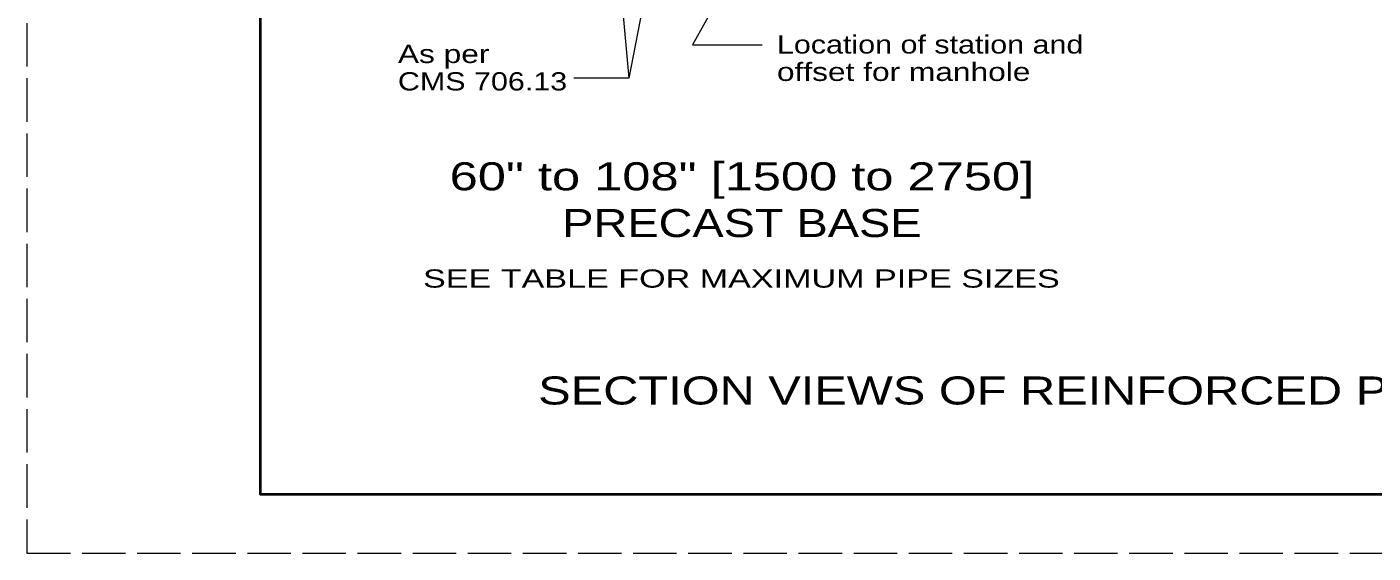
# Model space of a CAD drawing. Extents: x 808.4 to 842.4, y 1034.6 to 1056.6.
# Drawn here: x 808.44 to 819.97, y 1034.63 to 1039.13 of the extents above; entities that cross this region are included whole.
import ezdxf
from ezdxf.enums import TextEntityAlignment as Align

# ---------------------------------------------------------------- set-up
doc = ezdxf.new("R2010")
doc.units = 0
doc.header["$LTSCALE"] = 0.062
doc.linetypes.add('LONG_DASHED', pattern=[7.5, 6, -1.5])
doc.layers.add('1', color=7, linetype='Continuous', lineweight=13)
doc.layers.add('10', color=7, linetype='Continuous')

msp = doc.modelspace()

# ---------------------------------------------------------------- linework, layer by layer
at = {"layer": '1'}
msp.add_line((813.82633, 1039.8885), (813.592, 1038.69192), dxfattribs=at)
at = {"layer": '1', "linetype": 'LONG_DASHED'}
msp.add_lwpolyline([(808.43883, 1034.62767), (842.43883, 1034.62767), (842.43883, 1056.62767), (808.43883, 1056.62767)], close=True, dxfattribs=at)
at = {"layer": '1', "lineweight": 25}
msp.add_lwpolyline([(810.43883, 1056.12767), (841.93883, 1056.12767), (841.93883, 1035.12767), (810.43883, 1035.12767)], close=True, dxfattribs=at)
at = {"layer": '1', "lineweight": 40}
msp.add_lwpolyline([(810.43883, 1056.12767), (841.93883, 1056.12767), (841.93883, 1035.12767), (810.43883, 1035.12767)], close=True, dxfattribs=at)
at = {"layer": '1'}
for points in [[(814.62692, 1039.89542), (814.72483, 1040.02425), (814.13883, 1038.97683), (814.73583, 1038.97683)], [(813.48992, 1039.82542), (813.592, 1038.69192), (813.12325, 1038.69192)]]:
    msp.add_lwpolyline(points, dxfattribs=at)

# ---------------------------------------------------------------- texts
for s, width, p in [('Location of station and', 1.25, (814.86167, 1038.9035)), ('offset for manhole', 1.3, (814.86167, 1038.66883))]:
    msp.add_text(s, height=0.156, dxfattribs=dict(at, width=width)).set_placement(p)
at = {"layer": '10'}
for s, height, width, p in [('As per', 0.156, 1.3, (811.61567, 1038.82217)), ('CMS 706.13', 0.156, 1.25, (811.61567, 1038.5875)), ('SEE TABLE FOR MAXIMUM PIPE SIZES', 0.156, 1.4, (811.83092, 1036.89967)), ('SECTION VIEWS OF REINFORCED PRECAST MANHOLES', 0.24, 1.3, (812.81725, 1035.89925))]:
    msp.add_text(s, height=height, dxfattribs=dict(at, width=width)).set_placement(p)
for s, width, p in [('60" to 108" [1500 to 2750]', 1.35, (814.56162, 1037.73258)), ('PRECAST BASE', 1.25, (814.56162, 1037.33258))]:
    msp.add_text(s, height=0.24, dxfattribs=dict(at, width=width)).set_placement(p, align=Align.CENTER)

doc.saveas('drawing.dxf')
